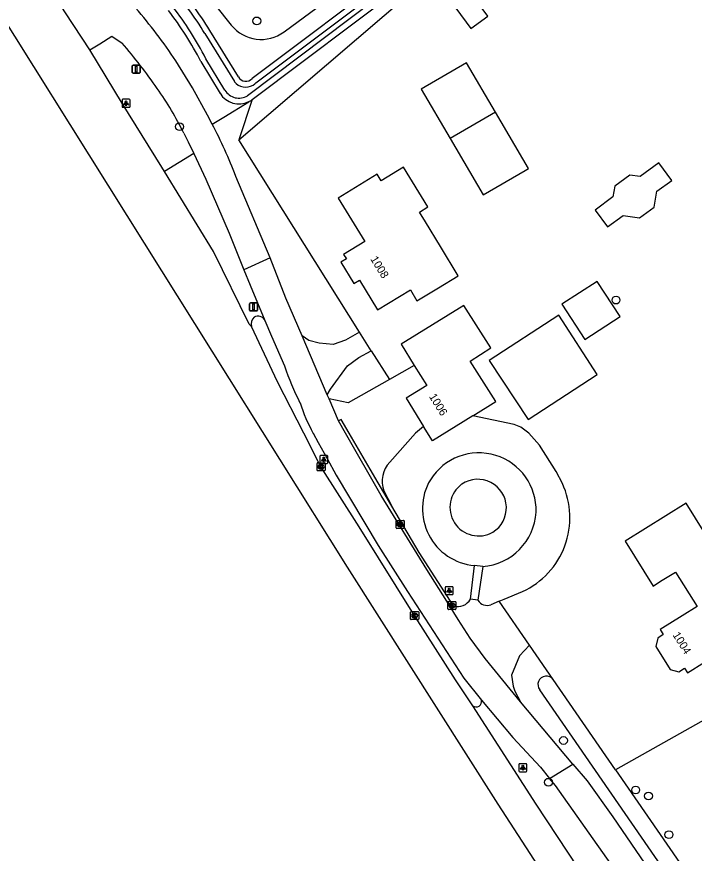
# Model space of a CAD drawing. Extents: x 157767 to 159171, y 387842 to 389425.
# Drawn here: x 158319.7 to 158404.2, y 387947.5 to 388052.1 of the extents above; entities that cross this region are included whole.
import ezdxf

# ---------------------------------------------------------------- set-up
doc = ezdxf.new("R2010")
doc.units = 0
for name, color, linetype in [('IMGEO_Berm_groen', 7, 'Continuous'), ('IMGEO_Berm_open', 7, 'Continuous'), ('IMGEO_Boom', 7, 'Continuous'), ('IMGEO_Fietspad_gesloten', 7, 'Continuous'), ('IMGEO_Fietspad_open', 7, 'Continuous'), ('IMGEO_Groenvoorziening', 7, 'Continuous'), ('IMGEO_Hek', 7, 'Continuous'), ('IMGEO_Kolk', 7, 'Continuous'), ('IMGEO_Lichtpunt', 7, 'Continuous'), ('IMGEO_Pand', 7, 'Continuous'), ('IMGEO_Pand_nummerreeks', 7, 'Continuous'), ('IMGEO_Rijbaan_lokaal_open', 7, 'Continuous'), ('IMGEO_Rijbaan_regionaal_gesloten', 7, 'Continuous'), ('IMGEO_Verkeersbordpaal', 7, 'Continuous'), ('IMGEO_Verkeerseiland_groen', 7, 'Continuous'), ('IMGEO_Voetpad_halfverhard', 7, 'Continuous'), ('IMGEO_Voetpad_op_trap', 7, 'Continuous'), ('IMGEO_Voetpad_open', 7, 'Continuous'), ('IMGEO_Waterloop', 7, 'Continuous')]:
    doc.layers.add(name, color=color, linetype=linetype)

msp = doc.modelspace()

# ---------------------------------------------------------------- linework, layer by layer
at = {"layer": 'IMGEO_Berm_groen'}
for points in [[(158342.64, 388046.44), (158345.04, 388042.48)], [(158344.05, 388038.63), (158345.5, 388039.52), (158348.61, 388041.43)], [(158349.06, 388041.71), (158347.36, 388036.66)], [(158362.46, 388012.62), (158347.36, 388036.66)]]:
    msp.add_lwpolyline(points, dxfattribs=at)
for centre, radius, start, end in [((158303.64, 388026.23), 43.93, 27.3895, 37.2968), ((158347.4, 388043.91), 2.75, 211.2137, 296.1463), ((158347.4, 388043.9), 2.75, 296.2088, 307.0784)]:
    msp.add_arc(centre, radius, start, end, dxfattribs=at)
at = {"layer": 'IMGEO_Berm_open'}
for centre, radius, start, end in [((158349.94, 388013.72), 1.03, 128.9037, 201.3181), ((158349.77, 388013.7), 0.952, 24.3688, 120.0954), ((158377.01, 387966.48), 0.673, 230.2422, 16.3727)]:
    msp.add_arc(centre, radius, start, end, dxfattribs=at)
at = {"layer": 'IMGEO_Boom'}
for centre in [(158349.62, 388051.53), (158339.98, 388038.32), (158394.47, 388016.65), (158387.91, 387961.62), (158386.04, 387956.4), (158396.92, 387955.44), (158398.52, 387954.69), (158401.07, 387949.86)]:
    msp.add_circle(centre, 0.489, dxfattribs=at)
at = {"layer": 'IMGEO_Fietspad_gesloten'}
for points in [[(158328.76, 388047.9), (158330.04, 388048.68), (158331.53, 388049.62), (158332.81, 388048.76)], [(158344.05, 388038.63), (158343.46, 388039.74), (158341.58, 388043.19), (158339.52, 388046.53)], [(158340.51, 388037.49), (158341.06, 388036.41), (158341.77, 388034.97)], [(158341.77, 388034.97), (158343.24, 388031.74), (158346.17, 388024.99), (158348.02, 388020.44)], [(158351.3, 388021.92), (158346.99, 388032.11)], [(158351.3, 388021.92), (158348.02, 388020.44)], [(158386.18, 387956.88), (158389.08, 387958.68)], [(158389.08, 387958.68), (158390.87, 387956.57), (158394.09, 387952.07), (158438.68, 387886.74)], [(158420.01, 387908.01), (158415.77, 387914.21), (158409.21, 387923.86), (158403.56, 387932.02), (158397, 387941.7), (158393.84, 387946.22), (158386.9, 387955.99), (158386.18, 387956.88)]]:
    msp.add_lwpolyline(points, dxfattribs=at)
for centre, radius, start, end in [((158285.78, 388011.01), 64.41, 33.4665, 40.8455), ((158280.05, 388003.46), 69.54, 34.7299, 40.6477), ((158305.39, 388020.42), 39.05, 25.9205, 35.4656), ((158292.95, 388011.7), 57.77, 20.6902, 27.788)]:
    msp.add_arc(centre, radius, start, end, dxfattribs=at)
at = {"layer": 'IMGEO_Fietspad_open'}
for points in [[(158355.27, 388012.19), (158353.26, 388016.87), (158351.3, 388021.92)], [(158348.02, 388020.44), (158348.81, 388018.52), (158350.63, 388014.09)], [(158350.63, 388014.09), (158351.45, 388012.13), (158353.1, 388008.42)], [(158358.64, 388004.31), (158358.42, 388004.82)], [(158359.83, 388001.55), (158358.64, 388004.31)], [(158373.35, 387979.01), (158370.86, 387982.98), (158365.14, 387992.23), (158360.69, 388000), (158359.83, 388001.55)], [(158356.65, 388000), (158357.3, 387998.86), (158358.42, 387996.85), (158359.52, 387994.79), (158364.77, 387985.98), (158368.45, 387980.23), (158375.48, 387969.39), (158377.66, 387966.67)], [(158382.54, 387966.47), (158378.15, 387971.85), (158376.25, 387974.42), (158374.77, 387976.74), (158373.35, 387979.01)], [(158377.66, 387966.67), (158381.59, 387962.01), (158385.06, 387958.27), (158386.18, 387956.88)], [(158389.08, 387958.68), (158382.54, 387966.47)]]:
    msp.add_lwpolyline(points, dxfattribs=at)
for centre, radius, start, end in [((158386.09, 388019.43), 34.78, 198.4632, 206.6738), ((158377.51, 388011.2), 23.67, 198.1735, 208.2454)]:
    msp.add_arc(centre, radius, start, end, dxfattribs=at)
at = {"layer": 'IMGEO_Groenvoorziening'}
for points in [[(158286.56, 388136.84), (158289.95, 388131.84), (158293.14, 388126.7), (158301.08, 388113.01), (158313.13, 388093.62), (158318.76, 388085.94), (158320.39, 388083.38), (158325.54, 388074.48), (158328.97, 388069.8), (158330.49, 388068.17), (158335.89, 388063.12), (158338.61, 388060.87), (158346.44, 388051.01)], [(158347.36, 388036.66), (158380.2, 388064.83)], [(158353.04, 388050.17), (158372.86, 388064.81)], [(158372.51, 388061.79), (158367.21, 388058.05), (158349.03, 388044.35)], [(158349.06, 388041.71), (158367.96, 388056.01), (158373.87, 388060.27)], [(158347.32, 388044.53), (158343.75, 388050.35)], [(158363.92, 388010.3), (158366.17, 388006.72)], [(158387.78, 387993.73), (158386.98, 387995.22), (158384.92, 387998.54), (158383.58, 388000), (158382.6, 388000.75), (158381.76, 388001.1), (158376.61, 388002.18)], [(158379.88, 387979.02), (158380.49, 387979.28), (158382.8, 387980.24)], [(158386.63, 387969.24), (158383.68, 387973.51)], [(158412.38, 387968.07), (158394.4, 387957.97)]]:
    msp.add_lwpolyline(points, dxfattribs=at)
for centre, radius, start, end in [((158312.68, 388031.81), 36.17, 30.8277, 42.5683), ((158350.17, 388054.02), 4.8, 218.8613, 306.6279), ((158348.24, 388045.02), 1.04, 208.1157, 319.786), ((158378.57, 387989.46), 10.14, 294.6285, 24.8947)]:
    msp.add_arc(centre, radius, start, end, dxfattribs=at)
at = {"layer": 'IMGEO_Hek'}
for points in [[(158383.68, 387973.51), (158379.88, 387979.02)], [(158386.63, 387969.24), (158383.68, 387973.51)]]:
    msp.add_lwpolyline(points, dxfattribs=at)
at = {"layer": 'IMGEO_Kolk'}
for p, q in [((158357.14, 387995.4), (158357.14, 387996.25)), ((158357.22, 387996.32), (158358.07, 387996.32)), ((158358.14, 387996.25), (158358.14, 387995.4)), ((158358.07, 387995.32), (158357.22, 387995.32)), ((158357.63, 387996.1), (158357.66, 387996.1)), ((158357.65, 387995.54), (158357.63, 387995.54)), ((158367.01, 387988.2), (158367.01, 387989.05)), ((158367.08, 387989.12), (158367.94, 387989.12)), ((158367.5, 387988.9), (158367.52, 387988.9)), ((158368.01, 387989.05), (158368.01, 387988.2)), ((158367.94, 387988.12), (158367.08, 387988.12)), ((158367.52, 387988.34), (158367.49, 387988.34)), ((158373.48, 387978.06), (158373.48, 387978.91)), ((158373.56, 387978.98), (158374.41, 387978.98)), ((158373.97, 387978.76), (158373.99, 387978.76)), ((158374.48, 387978.91), (158374.48, 387978.06)), ((158368.82, 387976.8), (158368.82, 387977.65)), ((158368.9, 387977.73), (158369.75, 387977.73)), ((158369.31, 387977.51), (158369.34, 387977.51)), ((158369.83, 387977.65), (158369.83, 387976.8)), ((158374.41, 387977.98), (158373.56, 387977.98)), ((158373.99, 387978.2), (158373.97, 387978.2)), ((158369.75, 387976.73), (158368.9, 387976.73)), ((158369.33, 387976.95), (158369.31, 387976.95))]:
    msp.add_line(p, q, dxfattribs=at)
for points in [[(158357.14, 387995.4), (158357.14, 387996.25)], [(158357.22, 387996.32), (158358.07, 387996.32)], [(158358.14, 387996.25), (158358.14, 387995.4)], [(158358.07, 387995.32), (158357.22, 387995.32)], [(158357.46, 387996.02), (158357.59, 387996.02), (158357.59, 387995.87), (158357.72, 387996.02), (158357.88, 387996.02), (158357.74, 387995.87), (158357.89, 387995.62), (158357.74, 387995.62), (158357.65, 387995.79), (158357.59, 387995.72), (158357.59, 387995.62), (158357.46, 387995.62), (158357.46, 387996.02)], [(158367.01, 387988.2), (158367.01, 387989.05)], [(158367.08, 387989.12), (158367.94, 387989.12)], [(158368.01, 387989.05), (158368.01, 387988.2)], [(158367.94, 387988.12), (158367.08, 387988.12)], [(158367.33, 387988.82), (158367.45, 387988.82), (158367.45, 387988.67), (158367.58, 387988.82), (158367.75, 387988.82), (158367.6, 387988.67), (158367.75, 387988.42), (158367.6, 387988.42), (158367.52, 387988.59), (158367.45, 387988.52), (158367.45, 387988.42), (158367.33, 387988.42), (158367.33, 387988.82)], [(158373.48, 387978.06), (158373.48, 387978.91)], [(158373.56, 387978.98), (158374.41, 387978.98)], [(158373.8, 387978.68), (158373.93, 387978.68), (158373.93, 387978.53), (158374.05, 387978.68), (158374.22, 387978.68), (158374.07, 387978.53), (158374.23, 387978.28), (158374.07, 387978.28), (158373.99, 387978.45), (158373.93, 387978.38), (158373.93, 387978.28), (158373.8, 387978.28), (158373.8, 387978.68)], [(158374.48, 387978.91), (158374.48, 387978.06)], [(158368.82, 387976.8), (158368.82, 387977.65)], [(158368.9, 387977.73), (158369.75, 387977.73)], [(158369.14, 387977.43), (158369.27, 387977.43), (158369.27, 387977.28), (158369.4, 387977.43), (158369.56, 387977.43), (158369.42, 387977.28), (158369.57, 387977.03), (158369.42, 387977.03), (158369.33, 387977.19), (158369.27, 387977.12), (158369.27, 387977.03), (158369.14, 387977.03), (158369.14, 387977.43)], [(158369.83, 387977.65), (158369.83, 387976.8)], [(158374.41, 387977.98), (158373.56, 387977.98)], [(158369.75, 387976.73), (158368.9, 387976.73)]]:
    msp.add_lwpolyline(points, dxfattribs=at)
for centre, start, end in [((158357.22, 387996.25), 91.552, 178.448), ((158357.22, 387996.25), 91.552, 178.448), ((158358.07, 387996.25), 1.552, 88.448), ((158358.07, 387996.25), 1.552, 88.448), ((158357.22, 387995.4), 181.552, 268.448), ((158357.22, 387995.4), 181.552, 268.448), ((158358.07, 387995.4), 271.552, 358.448), ((158358.07, 387995.4), 271.552, 358.448), ((158367.09, 387989.05), 91.552, 178.448), ((158367.09, 387989.05), 91.552, 178.448), ((158367.93, 387989.05), 1.552, 88.448), ((158367.93, 387989.05), 1.552, 88.448), ((158367.09, 387988.2), 181.552, 268.448), ((158367.09, 387988.2), 181.552, 268.448), ((158367.93, 387988.2), 271.552, 358.448), ((158367.93, 387988.2), 271.552, 358.448), ((158373.56, 387978.91), 91.552, 178.448), ((158373.56, 387978.91), 91.552, 178.448), ((158374.41, 387978.91), 1.552, 88.448), ((158374.41, 387978.91), 1.552, 88.448), ((158368.9, 387977.65), 91.552, 178.448), ((158368.9, 387977.65), 91.552, 178.448), ((158369.75, 387977.65), 1.552, 88.448), ((158369.75, 387977.65), 1.552, 88.448), ((158373.56, 387978.06), 181.552, 268.448), ((158373.56, 387978.06), 181.552, 268.448), ((158374.41, 387978.06), 271.552, 358.448), ((158374.41, 387978.06), 271.552, 358.448), ((158368.9, 387976.8), 181.552, 268.448), ((158368.9, 387976.8), 181.552, 268.448), ((158369.75, 387976.8), 271.552, 358.448), ((158369.75, 387976.8), 271.552, 358.448)]:
    msp.add_arc(centre, 0.0765, start, end, dxfattribs=at)
for centre, major_axis, ratio, start_param, end_param in [((158357.63, 387995.82), (-0.387, 0.002), 0.722429, 4.712389, 7.853982), ((158357.65, 387995.82), (-0.39, 0.002), 0.717154, 1.570796, 4.712389), ((158367.5, 387988.62), (-0.387, 0.002), 0.722429, 4.712389, 7.853982), ((158367.52, 387988.62), (-0.39, 0.002), 0.717154, 1.570796, 4.712389), ((158373.97, 387978.48), (-0.387, 0.002), 0.722429, 4.712389, 7.853982), ((158373.99, 387978.48), (-0.39, 0.002), 0.717154, 1.570796, 4.712389), ((158369.31, 387977.23), (-0.387, 0.002), 0.722429, 4.712389, 7.853982), ((158369.34, 387977.23), (-0.39, 0.002), 0.717154, 1.570796, 4.712389)]:
    msp.add_ellipse(centre, major_axis=major_axis, ratio=ratio, start_param=start_param, end_param=end_param, dxfattribs=at)
at = {"layer": 'IMGEO_Lichtpunt'}
for p, q in [((158332.8, 388041.64), (158332.8, 388040.83)), ((158332.8, 388041.64), (158332.8, 388040.83)), ((158333.7, 388041.74), (158332.89, 388041.74)), ((158333.7, 388041.74), (158332.89, 388041.74)), ((158333.8, 388040.83), (158333.8, 388041.64)), ((158333.8, 388040.83), (158333.8, 388041.64)), ((158332.89, 388040.74), (158333.7, 388040.74)), ((158332.89, 388040.74), (158333.7, 388040.74)), ((158358.39, 387997.24), (158357.58, 387997.24)), ((158358.39, 387997.24), (158357.58, 387997.24)), ((158357.49, 387997.14), (158357.49, 387996.33)), ((158357.49, 387997.14), (158357.49, 387996.33)), ((158357.58, 387996.24), (158358.39, 387996.24)), ((158357.58, 387996.24), (158358.39, 387996.24)), ((158358.49, 387996.33), (158358.49, 387997.14)), ((158358.49, 387996.33), (158358.49, 387997.14)), ((158373.14, 387980.75), (158373.14, 387979.94)), ((158373.14, 387980.75), (158373.14, 387979.94)), ((158374.04, 387980.84), (158373.24, 387980.84)), ((158374.04, 387980.84), (158373.24, 387980.84)), ((158374.14, 387979.94), (158374.14, 387980.75)), ((158374.14, 387979.94), (158374.14, 387980.75)), ((158373.24, 387979.85), (158374.04, 387979.85)), ((158373.24, 387979.85), (158374.04, 387979.85)), ((158382.34, 387958.62), (158382.34, 387957.81)), ((158382.34, 387958.62), (158382.34, 387957.81)), ((158383.24, 387958.71), (158382.44, 387958.71)), ((158383.24, 387958.71), (158382.44, 387958.71)), ((158383.34, 387957.81), (158383.34, 387958.62)), ((158383.34, 387957.81), (158383.34, 387958.62)), ((158382.44, 387957.72), (158383.24, 387957.72)), ((158382.44, 387957.72), (158383.24, 387957.72))]:
    msp.add_line(p, q, dxfattribs=at)
for points in [[(158333.17, 388041.3), (158333.21, 388041.28), (158333.02, 388041.01), (158332.99, 388041.04), (158333.17, 388041.3)], [(158333.27, 388041.26), (158333.32, 388041.26), (158333.32, 388040.93), (158333.27, 388040.93), (158333.27, 388041.26)], [(158333.38, 388041.28), (158333.42, 388041.3), (158333.61, 388041.04), (158333.57, 388041.01), (158333.38, 388041.28)], [(158357.86, 387996.8), (158357.9, 387996.78), (158357.72, 387996.51), (158357.68, 387996.54), (158357.86, 387996.8)], [(158357.97, 387996.76), (158358.01, 387996.76), (158358.01, 387996.43), (158357.97, 387996.43), (158357.97, 387996.76)], [(158358.08, 387996.78), (158358.11, 387996.8), (158358.3, 387996.54), (158358.26, 387996.51), (158358.08, 387996.78)], [(158373.52, 387980.41), (158373.55, 387980.39), (158373.37, 387980.12), (158373.33, 387980.15), (158373.52, 387980.41)], [(158373.62, 387980.37), (158373.66, 387980.37), (158373.66, 387980.04), (158373.62, 387980.04), (158373.62, 387980.37)], [(158373.73, 387980.39), (158373.77, 387980.41), (158373.95, 387980.15), (158373.91, 387980.12), (158373.73, 387980.39)], [(158382.72, 387958.28), (158382.75, 387958.26), (158382.57, 387957.99), (158382.53, 387958.02), (158382.72, 387958.28)], [(158382.82, 387958.24), (158382.87, 387958.24), (158382.87, 387957.91), (158382.82, 387957.91), (158382.82, 387958.24)], [(158382.93, 387958.26), (158382.97, 387958.28), (158383.15, 387958.02), (158383.11, 387957.99), (158382.93, 387958.26)]]:
    msp.add_lwpolyline(points, dxfattribs=at)
for centre in [(158333.3, 388041.44), (158357.99, 387996.94), (158373.64, 387980.55), (158382.84, 387958.42)]:
    msp.add_circle(centre, 0.0994, dxfattribs=at)
for centre, start, end in [((158332.89, 388041.64), 90, 180), ((158332.89, 388041.64), 90, 180), ((158333.7, 388041.64), 0, 90), ((158333.7, 388041.64), 0, 90), ((158332.89, 388040.83), 180, 270), ((158332.89, 388040.83), 180, 270), ((158333.7, 388040.83), 270, 0), ((158333.7, 388040.83), 270, 360), ((158357.58, 387997.14), 90, 180), ((158357.58, 387997.14), 90, 180), ((158358.39, 387997.14), 0, 90), ((158358.39, 387997.14), 0, 90), ((158357.58, 387996.33), 180, 270), ((158357.58, 387996.33), 180, 270), ((158358.39, 387996.33), 270, 0), ((158358.39, 387996.33), 270, 360), ((158373.24, 387980.75), 90, 180), ((158373.24, 387980.75), 90, 180), ((158374.04, 387980.75), 0, 90), ((158374.04, 387980.75), 0, 90), ((158373.24, 387979.94), 180, 270), ((158373.24, 387979.94), 180, 270), ((158374.04, 387979.94), 270, 0), ((158374.04, 387979.94), 270, 360), ((158382.44, 387958.62), 90, 180), ((158382.44, 387958.62), 90, 180), ((158383.24, 387958.62), 0, 90), ((158383.24, 387958.62), 0, 90), ((158382.44, 387957.81), 180, 270), ((158382.44, 387957.81), 180, 270), ((158383.24, 387957.81), 270, 0), ((158383.24, 387957.81), 270, 360)]:
    msp.add_arc(centre, 0.0946, start, end, dxfattribs=at)
at = {"layer": 'IMGEO_Pand'}
for points in [[(158373.17, 388054.91), (158376.33, 388050.58), (158378.45, 388052.13), (158375.28, 388056.45), (158373.17, 388054.91)], [(158379.43, 388040.11), (158375.81, 388046.31), (158370.16, 388043.01), (158373.78, 388036.82)], [(158379.43, 388040.11), (158373.78, 388036.82)], [(158373.78, 388036.82), (158377.88, 388029.79), (158383.11, 388032.84), (158383.53, 388033.09), (158379.43, 388040.11)], [(158372.54, 388023.34), (158370.67, 388026.42), (158369.92, 388027.65), (158370.99, 388028.31), (158367.92, 388033.27), (158365.16, 388031.55), (158364.63, 388032.4), (158359.77, 388029.4), (158363.13, 388023.98), (158360.45, 388022.35), (158360.8, 388021.79), (158360.12, 388021.38), (158361.74, 388018.71), (158362.46, 388019.14), (158364.7, 388015.45), (158368.79, 388017.93), (158369.62, 388016.57), (158372.31, 388018.2), (158374.76, 388019.68), (158372.54, 388023.34)], [(158391.86, 388027.89), (158393.42, 388025.79), (158395.34, 388027.21), (158397.41, 388026.92), (158399.22, 388028.26), (158399.58, 388030.25), (158401.42, 388031.61), (158399.81, 388033.79), (158397.49, 388032.07), (158396.18, 388032.25), (158394.32, 388030.87), (158394.07, 388029.53), (158391.86, 388027.89)], [(158387.71, 388016.14), (158390.58, 388011.72), (158394.97, 388014.58), (158392.1, 388018.99), (158387.71, 388016.14)], [(158376.61, 388002.18), (158379.47, 388003.97), (158376.26, 388009.03), (158378.85, 388010.68), (158375.48, 388015.99), (158367.64, 388011.16), (158369.28, 388008.48)], [(158383.48, 388001.71), (158392.12, 388007.37), (158387.32, 388014.75), (158378.63, 388009.1), (158383.48, 388001.71)], [(158369.28, 388008.48), (158370.84, 388005.96), (158368.25, 388004.38), (158370.45, 388000.84)], [(158376.61, 388002.18), (158371.56, 387999.05), (158370.45, 388000.84)], [(158406.42, 387971.98), (158407.61, 387972.72), (158411.55, 387975.18), (158408.14, 387980.59), (158405.45, 387984.89), (158406.71, 387985.67), (158403.21, 387991.27), (158395.59, 387986.51), (158399.09, 387980.92), (158400.04, 387981.51), (158401.89, 387982.67), (158404.58, 387978.37), (158402.73, 387977.21), (158399.98, 387975.49), (158400.37, 387974.86), (158399.67, 387974.42), (158399.43, 387973.35), (158401.23, 387970.47), (158402.29, 387970.21), (158403, 387970.66), (158403.37, 387970.07), (158404.06, 387970.5), (158406.42, 387971.98)]]:
    msp.add_lwpolyline(points, dxfattribs=at)
for centre, radius, start, end in [((158377.21, 387990.69), 3.57, 301.685, 123.5513), ((158377.32, 387990.76), 3.58, 125.6563, 299.5801)]:
    msp.add_arc(centre, radius, start, end, dxfattribs=at)
at = {"layer": 'IMGEO_Rijbaan_lokaal_open'}
for points in [[(158362.46, 388012.62), (158360.68, 388011.63), (158359.17, 388011.11), (158357.42, 388011.26), (158356.1, 388011.59), (158355.27, 388012.19)], [(158358.42, 388004.82), (158355.27, 388012.19)], [(158363.92, 388010.3), (158362.46, 388012.62)], [(158358.42, 388004.82), (158358.82, 388005.53), (158360.96, 388008.42), (158362.38, 388009.46), (158363.92, 388010.3)]]:
    msp.add_lwpolyline(points, dxfattribs=at)
at = {"layer": 'IMGEO_Rijbaan_regionaal_gesloten'}
for points in [[(158452.8, 387845.02), (158451.52, 387846.95), (158442.15, 387860.94), (158426.87, 387883.33), (158408.41, 387910.46), (158399.46, 387923.7), (158386.76, 387942.89), (158379.77, 387953.65), (158360.95, 387983.28), (158344.04, 388010.28), (158333.45, 388027.23), (158314.65, 388057.25), (158299.75, 388081.13), (158276.3, 388118.67), (158263.51, 388139.13), (158246.51, 388166.46), (158235.87, 388183.54), (158227.89, 388196.4)], [(158328.76, 388047.9), (158325.73, 388052.56), (158321.21, 388059.59)], [(158338.11, 388032.72), (158337.77, 388033.27), (158332.85, 388041.16), (158328.76, 388047.9)], [(158348.98, 388013.34), (158348.67, 388013.63), (158344.21, 388022.73), (158338.11, 388032.72)], [(158376.58, 387965.96), (158374.43, 387969.22), (158369.45, 387977.03), (158362.41, 387988.3), (158357.57, 387995.9), (158357.28, 387996.46), (158355.48, 388000), (158352.22, 388006.42), (158348.98, 388013.34)], [(158391.12, 387943.61), (158384.48, 387953.68), (158376.58, 387965.96)]]:
    msp.add_lwpolyline(points, dxfattribs=at)
at = {"layer": 'IMGEO_Verkeersbordpaal'}
for p, q in [((158334.08, 388045.1), (158334.08, 388045.9)), ((158334.08, 388045.9), (158334.08, 388045.1)), ((158334.18, 388046), (158334.97, 388046)), ((158334.97, 388046), (158334.18, 388046)), ((158335.07, 388045.9), (158335.07, 388045.1)), ((158335.07, 388045.1), (158335.07, 388045.9)), ((158334.97, 388045), (158334.18, 388045)), ((158334.18, 388045), (158334.97, 388045)), ((158348.72, 388015.39), (158348.72, 388016.19)), ((158348.72, 388016.19), (158348.72, 388015.39)), ((158348.82, 388016.29), (158349.61, 388016.29)), ((158349.61, 388016.29), (158348.82, 388016.29)), ((158349.71, 388016.19), (158349.71, 388015.39)), ((158349.71, 388015.39), (158349.71, 388016.19)), ((158349.61, 388015.29), (158348.82, 388015.29)), ((158348.82, 388015.29), (158349.61, 388015.29))]:
    msp.add_line(p, q, dxfattribs=at)
for points in [[(158334.5, 388045.87), (158334.65, 388045.87), (158334.65, 388045.12), (158334.5, 388045.12), (158334.5, 388045.87)], [(158349.14, 388016.17), (158349.29, 388016.17), (158349.29, 388015.42), (158349.14, 388015.42), (158349.14, 388016.17)]]:
    msp.add_lwpolyline(points, dxfattribs=at)
for centre, start, end in [((158334.18, 388045.9), 90, 180), ((158334.18, 388045.9), 90, 180), ((158334.97, 388045.9), 0, 90), ((158334.97, 388045.9), 360, 90), ((158334.18, 388045.1), 180, 270), ((158334.18, 388045.1), 180, 270), ((158334.97, 388045.1), 270, 0), ((158334.97, 388045.1), 270, 0), ((158348.82, 388016.19), 90, 180), ((158348.82, 388016.19), 90, 180), ((158349.61, 388016.19), 0, 90), ((158349.61, 388016.19), 360, 90), ((158348.82, 388015.39), 180, 270), ((158348.82, 388015.39), 180, 270), ((158349.61, 388015.39), 270, 0), ((158349.61, 388015.39), 270, 0)]:
    msp.add_arc(centre, 0.1, start, end, dxfattribs=at)
at = {"layer": 'IMGEO_Verkeerseiland_groen'}
msp.add_lwpolyline([(158341.77, 388034.97), (158338.11, 388032.72)], dxfattribs=at)
at = {"layer": 'IMGEO_Voetpad_halfverhard'}
msp.add_lwpolyline([(158377.82, 387983.34), (158376.78, 387983.47)], dxfattribs=at)
for centre, radius, start, end in [((158377.35, 387990.42), 7.14, 357.841, 148.0213), ((158377.44, 387990.58), 7.14, 149.4877, 264.726), ((158377.25, 387990.56), 7.24, 274.4456, 356.7443)]:
    msp.add_arc(centre, radius, start, end, dxfattribs=at)
at = {"layer": 'IMGEO_Voetpad_op_trap'}
for points in [[(158376.29, 387979.29), (158376.78, 387983.47)], [(158377.82, 387983.34), (158377.22, 387979.14)]]:
    msp.add_lwpolyline(points, dxfattribs=at)
at = {"layer": 'IMGEO_Voetpad_open'}
for points in [[(158369.28, 388008.48), (158366.17, 388006.72)], [(158366.17, 388006.72), (158361.04, 388003.82), (158358.64, 388004.31)], [(158366.48, 387990.88), (158363.76, 387995.53), (158361.16, 388000), (158360.15, 388001.73), (158359.83, 388001.55)], [(158370.45, 388000.84), (158369.43, 388000), (158366.22, 387996.41)], [(158365.5, 387992.82), (158366.48, 387990.88)], [(158374.19, 387978.44), (158369.91, 387985.09), (158366.48, 387990.88)], [(158377.22, 387979.14), (158376.29, 387979.29)], [(158379.88, 387979.02), (158378.84, 387978.59)], [(158383.68, 387973.51), (158379.88, 387979.02)], [(158383.68, 387973.51), (158382.41, 387972.2), (158381.42, 387969.79), (158381.61, 387968.42), (158381.82, 387967.79), (158382.54, 387966.47)]]:
    msp.add_lwpolyline(points, dxfattribs=at)
for centre, radius, start, end in [((158368.76, 387994.03), 3.48, 136.9136, 200.362), ((158374.72, 387980.15), 1.78, 219.6784, 252.6905), ((158374.72, 387980.15), 1.79, 252.7588, 331.2668), ((158378.36, 387979.83), 1.33, 211.2864, 291.1639)]:
    msp.add_arc(centre, radius, start, end, dxfattribs=at)
at = {"layer": 'IMGEO_Waterloop'}
for points in [[(158349.15, 388043.5), (158349.39, 388043.67), (158349.51, 388043.79), (158367.64, 388057.46), (158372.9, 388061.17)], [(158373.34, 388060.79), (158367.53, 388056.6), (158348.63, 388042.3), (158348.46, 388042.18)], [(158343.13, 388049.95), (158346.83, 388043.94)], [(158345.65, 388042.88), (158343.28, 388046.81)], [(158394.4, 387957.97), (158386.63, 387969.24)], [(158442.29, 387884.77), (158384.96, 387967.95)], [(158394.4, 387957.97), (158443.93, 387886.21)]]:
    msp.add_lwpolyline(points, dxfattribs=at)
for centre, radius, start, end in [((158312.54, 388031.69), 35.63, 30.8304, 42.5535), ((158303.75, 388026.32), 44.52, 27.4011, 37.3139), ((158348.24, 388045.04), 1.79, 217.9374, 300.6389), ((158347.4, 388043.91), 2.03, 210.5639, 301.3733), ((158385.78, 387968.61), 1.06, 36.4036, 219.1606)]:
    msp.add_arc(centre, radius, start, end, dxfattribs=at)

# ---------------------------------------------------------------- texts
at = {"layer": 'IMGEO_Pand_nummerreeks'}
for s, rotation, p in [('1008', 301.5603, (158363.76, 388021.78)), ('1006', 301.8767, (158371.08, 388004.6)), ('1004', 302.0447, (158401.49, 387974.81))]:
    msp.add_text(s, height=1, rotation=rotation, dxfattribs=at).set_placement(p)

doc.saveas('drawing.dxf')
